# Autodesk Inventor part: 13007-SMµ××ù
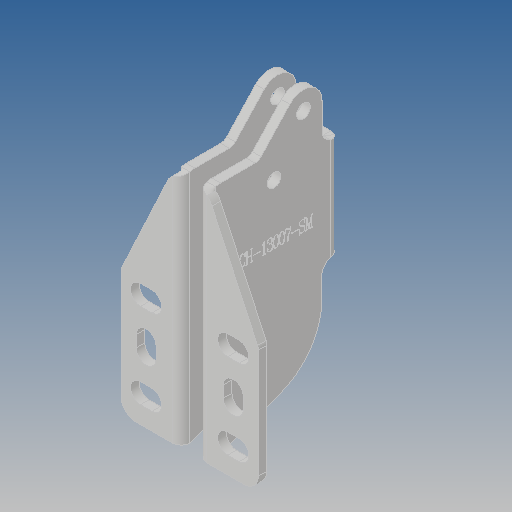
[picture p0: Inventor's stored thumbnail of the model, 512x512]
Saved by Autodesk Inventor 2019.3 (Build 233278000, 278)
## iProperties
Created: 2017-11
Part Number: 13007-SMµ××ù
Material: Ogólny
Document SubType Name: Modeling
Designer: Admin
Density: 1 g/cm^3
Appearance: Domyślna
Author: Admin
Revision Number: ÈÎºÎ
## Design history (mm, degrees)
feature "ÇÐ³ý-À­Éì1"
node "Bryła1"
